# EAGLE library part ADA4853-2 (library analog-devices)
Low Power, Rail-to-Rail Output, Video Op Amps with Ultralow Power Source: http://www.analog.com/static/imported-files/data_sheets/ADA4853-1_4853-2_4853-3.pdf
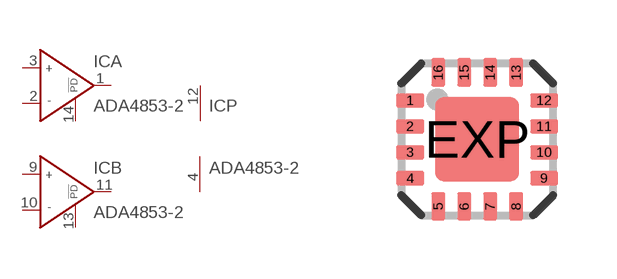
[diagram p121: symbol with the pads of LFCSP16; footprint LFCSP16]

Designator prefix IC; gates A=OP_PD B=OP_PD P=PWR+-

## ADA4853-2VQ (OC_FARNELL: unknown; OC_NEWARK: unknown)  [LFCSP16]
1  A:OUT  out
2  A:IN-  in
3  A:IN+  in
4  P:V-  pwr
9  B:IN+  in
10  B:IN-  in
11  B:OUT  out
12  P:V+  pwr
13  B:!POWERDOWN  pas
14  A:!POWERDOWN  pas

## Footprint LFCSP16 (pad centres in mm)
16-Terminal Leadless Frame Chip Scale Package [LFCSP] (CP) Source: Analog Devices .. 780914713ADD8704_0.pdf
smd 0.7 x 0.35: 1 -1.675,0.975; 2 -1.675,0.325; 3 -1.675,-0.325; 4 -1.675,-0.975; 9 1.675,-0.975; 10 1.675,-0.325; 11 1.675,0.325; 12 1.675,0.975
smd 0.35 x 0.7: 5 -0.975,-1.675; 6 -0.325,-1.675; 7 0.325,-1.675; 8 0.975,-1.675; 13 0.975,1.675; 14 0.325,1.675; 15 -0.325,1.675; 16 -0.975,1.675
smd 2.1 x 2.1: EXP 0,0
